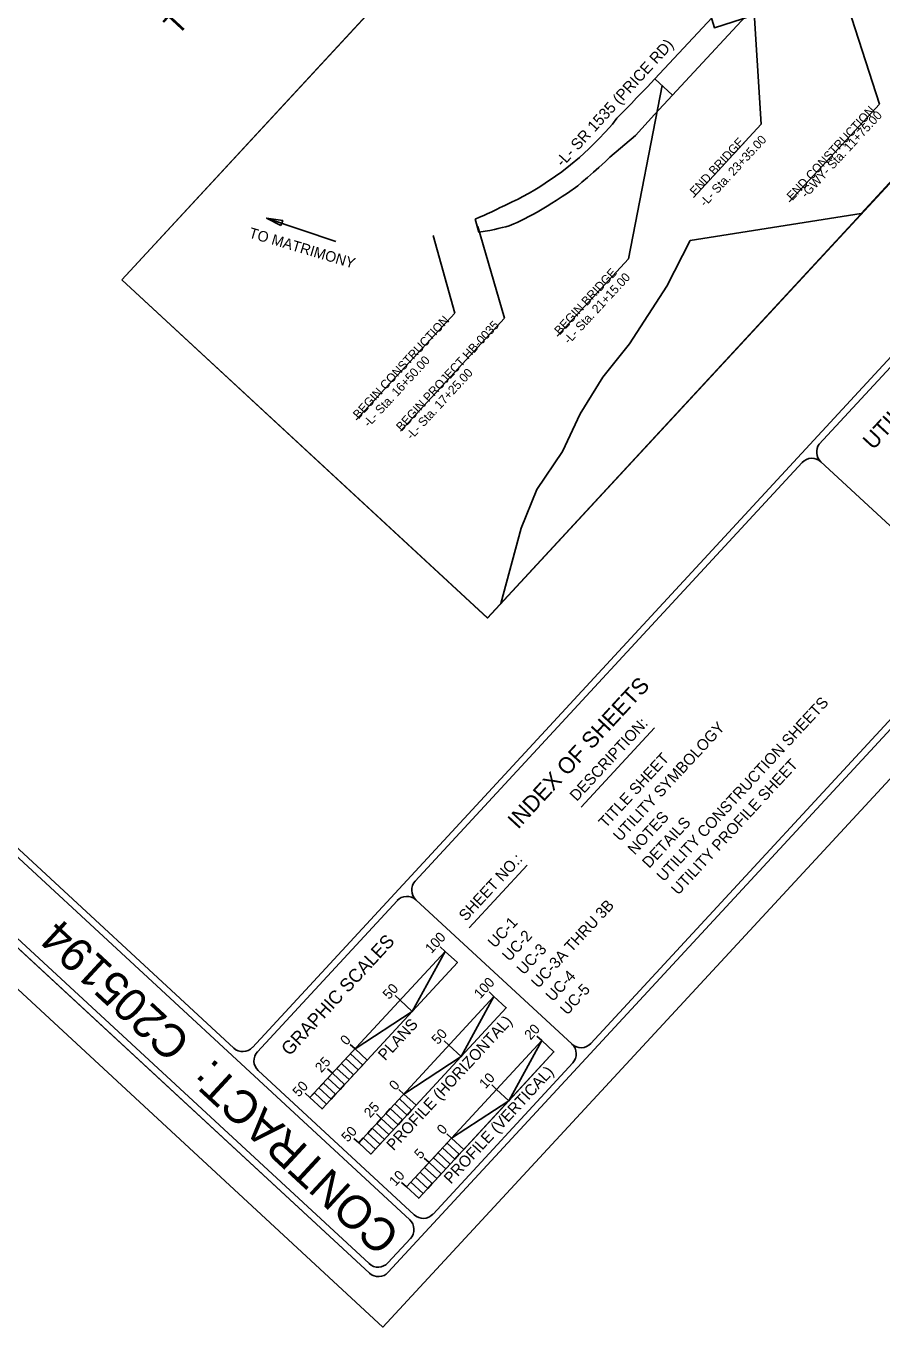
# Model space of a CAD drawing. Extents: x 1766669 to 1770980, y 998119 to 1002502.
# Drawn here: x 1767853 to 1769269, y 998119 to 1000271 of the extents above; entities that cross this region are included whole.
import ezdxf

# ---------------------------------------------------------------- set-up
doc = ezdxf.new("R2010")
doc.units = 0
for name, color, linetype in [('Default Symbol CELL', 7, 'Continuous'), ('Exist Control Text', 7, 'Continuous'), ('Exist Hydro Stream or Body of Water', 7, 'Continuous'), ('Exist Other Culture Area Outline', 7, 'Continuous'), ('Exist Roads Text', 7, 'Continuous'), ('Exist Survey Setup Group', 7, 'Continuous'), ('Exist Utilities Power Pole CELL', 7, 'Continuous'), ('PH Exist DTM Breakline', 7, 'Continuous')]:
    doc.layers.add(name, color=color, linetype=linetype)

msp = doc.modelspace()

# ---------------------------------------------------------------- linework, layer by layer
at = {"layer": 'Default Symbol CELL'}
for p, q in [((1768227.4, 998581.1), (1770560.1, 1001104.7)), ((1768451.9, 998209), (1770874.1, 1000829.4)), ((1768250.7, 999953), (1768365.3, 999914.4)), ((1769164.9, 999579.1), (1769441.1, 999878.1)), ((1768196.4, 998579.9), (1766849, 999825.3)), ((1768487.4, 998295.9), (1766841.5, 999817.2)), ((1768496.5, 998856), (1769136.7, 999548.6)), ((1769167.7, 999549.8), (1769425.9, 999311.1)), ((1768770.9, 998978.3), (1768892.2, 999109.6)), ((1768585.8, 998779), (1768681.8, 998882.5)), ((1768235.5, 998573.6), (1768466.7, 998823.7)), ((1768497.7, 998825), (1768755.9, 998586.3)), ((1768494.9, 998303.9), (1768236.7, 998542.6))]:
    msp.add_line(p, q, dxfattribs=at)
msp.add_lwpolyline([(1768274.3, 999940.4), (1768250.7, 999953), (1768277.2, 999948.7)], close=True, dxfattribs=at)
for points in [[(1766758.9, 999744.1), (1768420.8, 998207.8)], [(1766758.9, 999744), (1768420.9, 998207.7)], [(1766758.9, 999744), (1768420.9, 998207.7)], [(1766774.4, 999744.6), (1768420.3, 998223.3)], [(1768786.9, 998587.5), (1769427.1, 999280.1)], [(1768526, 998305.1), (1768757.1, 998555.3)], [(1768451.3, 998224.5), (1768488.6, 998264.8)]]:
    msp.add_lwpolyline(points, dxfattribs=at)
for centre, start, end in [((1769182.6, 999566), 143.3818, 227.2512), ((1769152.8, 999533.6), 47.2512, 137.2512), ((1768512.6, 998841.2), 137.2512, 227.2512), ((1768482.7, 998808.9), 47.2512, 137.2512), ((1768211.2, 998596.1), 227.2512, 317.2512), ((1768770.7, 998602.5), 227.2512, 317.2512), ((1768740.9, 998570.3), 317.2512, 47.2512), ((1768251.6, 998558.8), 137.2512, 227.2512), ((1768472.4, 998279.8), 317.2512, 47.2512), ((1768509.7, 998320.1), 227.2512, 317.2512), ((1768435.2, 998239.5), 227.2512, 317.2512), ((1768435.8, 998223.9), 227.2512, 317.2512)]:
    msp.add_arc(centre, 22, start, end, dxfattribs=at)
at = {"layer": 'Exist Control Text'}
msp.add_lwpolyline([(1768595.4, 999951.3), (1768602.8, 999954.2), (1768610.2, 999957.4), (1768615.4, 999959.7), (1768623.3, 999963.4), (1768630.9, 999967.1), (1768636.9, 999970.2), (1768639.5, 999971.5), (1768646.1, 999974.5), (1768657.1, 999979.6), (1768666.6, 999984.4), (1768673.6, 999988.1), (1768684.9, 999994.3), (1768694.2, 999999.8), (1768702.5, 1000004.8), (1768711.5, 1000010.5), (1768728.7, 1000022.3), (1768738.8, 1000029.7), (1768753.3, 1000040.9), (1768768.2, 1000053.4), (1768783.7, 1000067.4), (1768799.7, 1000083.2), (1768811.4, 1000095.6), (1768823.1, 1000108.2), (1768830.2, 1000118), (1768838.9, 1000126.9), (1768854.2, 1000142.7), (1768862.8, 1000151.6), (1768880.2, 1000169.6), (1768893, 1000183.3), (1768921.9, 1000156.4), (1768892.1, 1000124.4), (1768861, 1000089.5), (1768818.4, 1000053.8), (1768811.2, 1000046.7), (1768800.3, 1000036.5), (1768791.6, 1000028.7), (1768781.3, 1000019.9), (1768771.9, 1000012.2), (1768765.6, 1000006.1), (1768748.2, 999994.4), (1768739.8, 999988.7), (1768729.6, 999981.9), (1768722.7, 999977.4), (1768714.7, 999972.4), (1768703.7, 999965.9), (1768698.1, 999962.7), (1768691.1, 999958.9), (1768683.3, 999954.8), (1768678.6, 999952.3), (1768670.9, 999948.6), (1768664.9, 999945.7), (1768659.5, 999943.3), (1768651.8, 999940), (1768646.4, 999938.6), (1768640.4, 999937.1), (1768633.8, 999935.5), (1768627.4, 999934.1), (1768620.1, 999932.6), (1768612.1, 999931.1), (1768601.8, 999929.4)], close=True, dxfattribs=at)
at = {"layer": 'Exist Hydro Stream or Body of Water'}
for points in [[(1768977.3, 1000315.1), (1768991.4, 1000267.9), (1769068.6, 1000292.3)], [(1769389.3, 1000273.7), (1769413.2, 1000236.8), (1769434.5, 1000177.1), (1769413.6, 1000154.5), (1769388.7, 1000127.5), (1769373.5, 1000111.1), (1769347.6, 1000083), (1769313.2, 1000045.8), (1769261.5, 999989.9), (1769234.4, 999960.6), (1768951.6, 999915.7), (1768913, 999840.3), (1768851, 999744.9), (1768806.9, 999689.9), (1768769.6, 999629), (1768740.2, 999567), (1768697.9, 999504), (1768671.9, 999439.7), (1768638.1, 999315.6)]]:
    msp.add_lwpolyline(points, dxfattribs=at)
at = {"layer": 'Exist Roads Text'}
msp.add_lwpolyline([(1769042.7, 1000344.5), (1769071.7, 1000317.6), (1768921.9, 1000156.4), (1768893, 1000183.3)], close=True, dxfattribs=at)
at = {"layer": 'Exist Survey Setup Group'}
for p, q in [((1768546, 998739.9), (1768537.9, 998747.4)), ((1768546, 998739.9), (1768322.3, 998497.9)), ((1768566.2, 998721.3), (1768546, 998739.9)), ((1768342.4, 998479.2), (1768566.2, 998721.3)), ((1768626.8, 998665.2), (1768403.1, 998423.2)), ((1768471.4, 998659.3), (1768463.4, 998666.7)), ((1768626.8, 998665.2), (1768618.8, 998672.7)), ((1768647, 998646.6), (1768626.8, 998665.2)), ((1768423.3, 998404.5), (1768647, 998646.6)), ((1768471.4, 998659.3), (1768491.6, 998640.6)), ((1768705.8, 998592.3), (1768697.7, 998599.7)), ((1768396.9, 998578.6), (1768388.8, 998586)), ((1768705.8, 998592.3), (1768482, 998350.2)), ((1768552.3, 998584.5), (1768544.2, 998592)), ((1768552.3, 998584.5), (1768572.4, 998565.9)), ((1768725.9, 998573.6), (1768705.8, 998592.3)), ((1768374.5, 998554.4), (1768394.6, 998535.7)), ((1768502.2, 998331.6), (1768725.9, 998573.6)), ((1768359.6, 998538.2), (1768351.5, 998545.7)), ((1768477.7, 998503.8), (1768469.6, 998511.3)), ((1768631.2, 998511.6), (1768623.1, 998519)), ((1768631.2, 998511.6), (1768651.3, 998492.9)), ((1768322.3, 998497.9), (1768314.2, 998505.3)), ((1768314.2, 998505.3), (1768314.2, 998505.3)), ((1768322.3, 998497.9), (1768342.4, 998479.2)), ((1768322.3, 998497.9), (1768322.3, 998497.9)), ((1768440.4, 998463.5), (1768432.3, 998471)), ((1768455.3, 998479.7), (1768475.5, 998461)), ((1768403.1, 998423.2), (1768395.1, 998430.6)), ((1768395.1, 998430.6), (1768395.1, 998430.6)), ((1768556.6, 998430.9), (1768548.6, 998438.3)), ((1768403.1, 998423.2), (1768423.3, 998404.5)), ((1768403.1, 998423.2), (1768403.1, 998423.2)), ((1768534.2, 998406.7), (1768554.4, 998388.1)), ((1768519.3, 998390.5), (1768511.2, 998398)), ((1768482, 998350.2), (1768474, 998357.7)), ((1768474, 998357.7), (1768474, 998357.7)), ((1768482, 998350.2), (1768502.2, 998331.6)), ((1768482, 998350.2), (1768482, 998350.2))]:
    msp.add_line(p, q, dxfattribs=at)
for points in [[(1768011.1, 999850.8), (1769408.2, 1001362.3), (1770013.2, 1000803.1), (1768616, 999291.6)], [(1768011.1, 999850.8), (1769409.4, 1001362), (1770014.3, 1000802.4), (1768615.9, 999291.1)], [(1768546, 998739.9), (1768491.6, 998640.6), (1768566.2, 998721.3)], [(1768626.8, 998665.2), (1768572.4, 998565.9), (1768647, 998646.6)], [(1768396.9, 998578.6), (1768491.6, 998640.6), (1768417, 998559.9)], [(1768705.8, 998592.3), (1768651.3, 998492.9), (1768725.9, 998573.6)], [(1768367, 998546.3), (1768374.5, 998554.4), (1768394.6, 998535.7), (1768387.2, 998527.7)], [(1768381.9, 998562.4), (1768389.4, 998570.5), (1768409.6, 998551.8), (1768402.1, 998543.8)], [(1768477.7, 998503.8), (1768572.4, 998565.9), (1768497.9, 998485.2)], [(1768352.1, 998530.1), (1768359.6, 998538.2), (1768379.7, 998519.6), (1768372.3, 998511.5)], [(1768337.2, 998514), (1768344.7, 998522.1), (1768364.8, 998503.4), (1768357.4, 998495.4)], [(1768322.3, 998497.9), (1768329.7, 998506), (1768349.9, 998487.3), (1768342.4, 998479.2)], [(1768462.8, 998487.7), (1768470.2, 998495.8), (1768490.4, 998477.1), (1768482.9, 998469.1)], [(1768556.6, 998430.9), (1768651.3, 998492.9), (1768576.8, 998412.2)], [(1768447.9, 998471.6), (1768455.3, 998479.7), (1768475.5, 998461), (1768468, 998452.9)], [(1768418, 998439.3), (1768425.5, 998447.4), (1768445.7, 998428.7), (1768438.2, 998420.7)], [(1768432.9, 998455.4), (1768440.4, 998463.5), (1768460.6, 998444.9), (1768453.1, 998436.8)], [(1768403.1, 998423.2), (1768410.6, 998431.2), (1768430.7, 998412.6), (1768423.3, 998404.5)], [(1768526.8, 998398.6), (1768534.2, 998406.7), (1768554.4, 998388.1), (1768546.9, 998380)], [(1768541.7, 998414.8), (1768549.1, 998422.8), (1768569.3, 998404.2), (1768561.9, 998396.1)], [(1768511.9, 998382.5), (1768519.3, 998390.5), (1768539.5, 998371.9), (1768532, 998363.9)], [(1768496.9, 998366.4), (1768504.4, 998374.4), (1768524.6, 998355.8), (1768517.1, 998347.7)], [(1768482, 998350.2), (1768489.5, 998358.3), (1768509.7, 998339.6), (1768502.2, 998331.6)]]:
    msp.add_lwpolyline(points, close=True, dxfattribs=at)
at = {"layer": 'Exist Utilities Power Pole CELL'}
for p, q in [((1769264.6, 1000141.2), (1769199.4, 1000343.7)), ((1769054.5, 1000333.6), (1769069, 1000108.5)), ((1768849.5, 999885.3), (1768905.2, 1000172)), ((1769264.6, 1000141.2), (1769115.3, 999979.6)), ((1769069, 1000108.5), (1768956.7, 999987)), ((1768644.2, 999787.1), (1768599.9, 999938.8)), ((1768561.9, 999795.5), (1768526.4, 999924)), ((1768731.1, 999757.4), (1768849.5, 999885.3)), ((1768398.9, 999619.2), (1768561.9, 999795.5)), ((1768472, 999600.7), (1768644.2, 999787.1))]:
    msp.add_line(p, q, dxfattribs=at)
at = {"layer": 'PH Exist DTM Breakline'}
msp.add_lwpolyline([(1766668.6, 999760.2), (1769205.6, 1002501.9), (1770979.8, 1000860.3), (1768442.7, 998118.5)], close=True, dxfattribs=at)

# ---------------------------------------------------------------- texts
at = {"layer": 'Default Symbol CELL'}
for s, height, rotation, p in [('TYPE OF WORK: GRADING,  DRAINAGE,  PAVING, & STRUCTURE ', 35.736, 47.237, (1768103.6, 1000253.6)), ('-L- SR 1535 (PRICE RD)', 18.424, 47.6164, (1768740.6, 1000036.5)), ('TO MATRIMONY', 17.455, 343.4543, (1768220.1, 999921)), ('UTILITY OWNERS', 26.848, 47.237, (1769254.1, 999568.2)), ('INDEX OF SHEETS', 26.848, 47.237, (1768666.5, 998940.8)), ('UTILITY CONSTRUCTION SHEETS', 18.471, 47.237, (1768907.6, 998854.1)), ('DESCRIPTION:', 18.471, 47.237, (1768763.7, 998987.1)), ('UTILITY SYMBOLOGY', 18.471, 47.237, (1768835.7, 998920.6)), ('TITLE SHEET', 18.471, 47.237, (1768811.7, 998942.8)), ('UTILITY PROFILE SHEET', 18.471, 47.237, (1768931.6, 998832)), ('NOTES', 18.47, 47.237, (1768859.6, 998898.5)), ('DETAILS', 18.47, 47.237, (1768883.6, 998876.3)), ('SHEET NO.:', 18.47, 47.237, (1768580.2, 998788.6)), ('UC-3A THRU 3B', 18.471, 47.237, (1768700.1, 998677.8)), ('C205194', 54.93, 137.2512, (1768128, 998594)), ('UC-1', 18.47, 47.237, (1768628.2, 998744.3)), ('UC-2', 18.47, 47.237, (1768652.2, 998722.1)), ('GRAPHIC SCALES', 21.973, 47.2512, (1768288.7, 998565.8)), ('UC-3', 18.47, 47.237, (1768676.1, 998699.9)), ('UC-4', 18.47, 47.237, (1768724.1, 998655.6)), ('UC-5', 18.47, 47.237, (1768748, 998633.4)), ('CONTRACT:', 54.93, 137.2512, (1768474.5, 998273.7))]:
    msp.add_text(s, height=height, rotation=rotation, dxfattribs=at).set_placement(p)
at = {"layer": 'Exist Other Culture Area Outline'}
msp.add_text('-GWY- Sta. 11+75.00', height=14.543, rotation=47.2512, dxfattribs=at).set_placement((1769143.4, 999985))
at = {"layer": 'Exist Survey Setup Group'}
for s, height, p in [('100', 16.48, (1768523.3, 998735.3)), ('50', 16.48, (1768453.1, 998659.3)), ('100', 16.48, (1768604.1, 998660.5)), ('PLANS', 18.68, (1768446.7, 998558)), ('PROFILE (HORIZONTAL)', 18.677, (1768460.6, 998409.1)), ('20', 16.48, (1768687.4, 998592.3)), ('0', 16.5, (1768382.8, 998583.3)), ('50', 16.48, (1768533.9, 998584.6)), ('25', 16.48, (1768341.1, 998538.2)), ('PROFILE (VERTICAL)', 18.677, (1768555.5, 998354)), ('10', 16.48, (1768612.8, 998511.6)), ('50', 16.48, (1768303.9, 998497.9)), ('0', 16.5, (1768463.7, 998508.6)), ('25', 16.48, (1768422, 998463.4)), ('50', 16.48, (1768384.7, 998423.2)), ('0', 16.5, (1768542.6, 998435.6)), ('5', 16.5, (1768505.2, 998395.2)), ('10', 16.48, (1768463.7, 998350.2))]:
    msp.add_text(s, height=height, rotation=47.2512, dxfattribs=at).set_placement(p)
at = {"layer": 'Exist Utilities Power Pole CELL'}
for s, height, rotation, p in [('END CONSTRUCTION', 14.543, 47.2512, (1769120.3, 999980.9)), ('END BRIDGE', 14.54, 47.2512, (1768959.9, 999988.8)), ('-L- Sta. 23+35.00', 14.543, 47.2512, (1768976.3, 999970.9)), ('BEGIN BRIDGE', 14.543, 47.1775, (1768735.8, 999758.6)), ('-L- Sta. 21+15.00', 14.543, 47.1775, (1768750.9, 999743.4)), ('BEGIN CONSTRUCTION', 14.543, 47.2512, (1768402.7, 999619.6)), ('BEGIN PROJECT HB-0035', 14.543, 47.2512, (1768474, 999599.4)), ('-L- Sta. 16+50.00', 14.543, 47.2512, (1768419.6, 999605.9)), ('-L- Sta. 17+25.00', 14.543, 47.2512, (1768490.5, 999585.2))]:
    msp.add_text(s, height=height, rotation=rotation, dxfattribs=at).set_placement(p)

doc.saveas('drawing.dxf')
